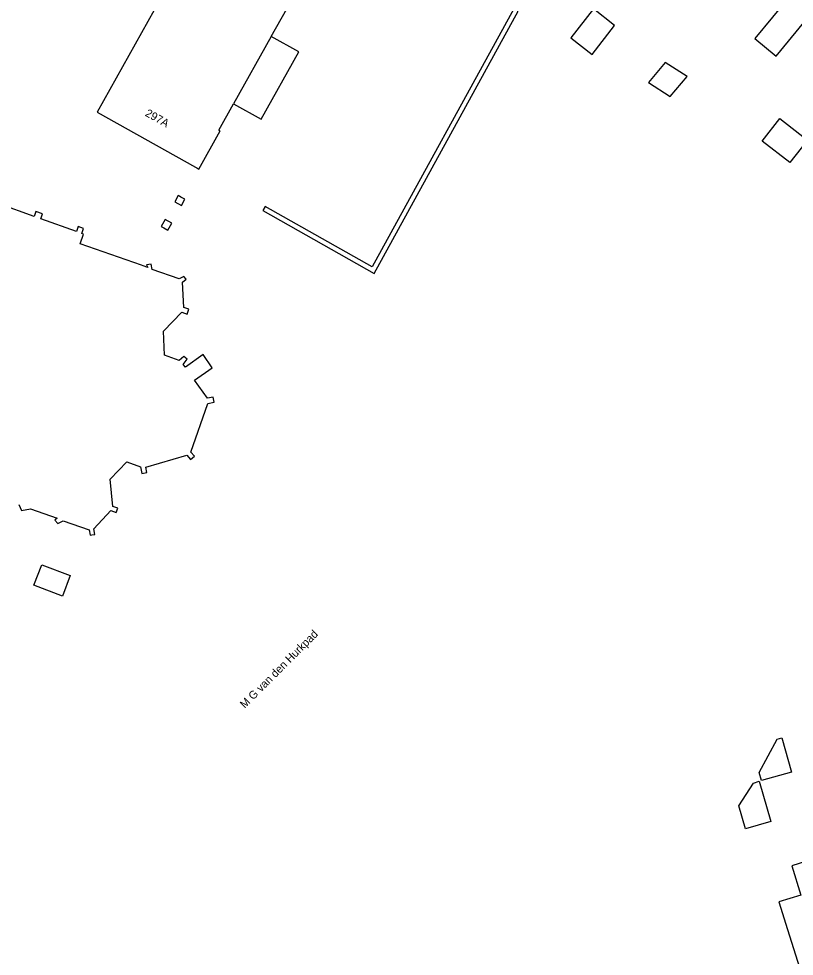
# Model space of a CAD drawing. Extents: x 160158 to 160921, y 381517 to 382041.
# Drawn here: x 160328.3 to 160425.2, y 381721.4 to 381838.6 of the extents above; entities that cross this region are included whole.
import ezdxf

# ---------------------------------------------------------------- set-up
doc = ezdxf.new("R2010")
doc.units = 0
for name, color, linetype in [('IMGEO_Haag', 7, 'Continuous'), ('IMGEO_Openbare_ruimte_label', 7, 'Continuous'), ('IMGEO_Pand', 7, 'Continuous'), ('IMGEO_Pand_nummerreeks', 7, 'Continuous')]:
    doc.layers.add(name, color=color, linetype=linetype)

msp = doc.modelspace()

# ---------------------------------------------------------------- linework, layer by layer
at = {"layer": 'IMGEO_Haag'}
msp.add_lwpolyline([(160390.71, 381839.51), (160390.18, 381839.81), (160372.47, 381807.57), (160359.11, 381815.11), (160358.81, 381814.59), (160372.7, 381806.75), (160390.71, 381839.51)], dxfattribs=at)
at = {"layer": 'IMGEO_Pand'}
for points in [[(160433.66, 381851.69), (160430.49, 381847.83), (160428.34, 381845.23), (160427.99, 381845.47), (160424.71, 381841.48), (160420.28, 381836.11), (160422.95, 381833.91), (160427.38, 381839.29), (160430.67, 381843.29), (160433.12, 381841.26), (160435.29, 381843.87), (160438.47, 381847.73)], [(160359.85, 381836.38), (160363.21, 381842.38), (160362.12, 381842.99), (160362.23, 381843.19), (160350.76, 381849.62), (160348.45, 381845.51), (160346.49, 381846.6), (160344.03, 381842.21), (160346.02, 381841.1), (160338.08, 381826.92), (160350.39, 381820.03), (160350.56, 381819.93), (160350.8, 381819.79), (160353.47, 381824.56), (160353.29, 381824.66), (160355.13, 381827.96)], [(160397.29, 381836.18), (160399.95, 381834.11), (160402.77, 381837.74), (160400.11, 381839.81), (160397.29, 381836.18)], [(160359.85, 381836.38), (160355.13, 381827.96)], [(160355.13, 381827.96), (160358.58, 381826.02), (160363.3, 381834.44), (160359.85, 381836.38)], [(160411.82, 381831.37), (160409.1, 381833.11), (160407, 381830.59), (160409.73, 381828.86), (160411.82, 381831.37)], [(160421.2, 381823.29), (160423.42, 381826.12), (160426.86, 381823.42), (160424.65, 381820.59), (160421.2, 381823.29)], [(160348.22, 381816.48), (160347.79, 381815.69), (160348.62, 381815.23), (160349.05, 381816.02), (160348.56, 381816.29), (160348.38, 381816.39), (160348.22, 381816.48)], [(160328.3, 381777.85), (160328.65, 381777.12), (160329.75, 381777.33), (160333.12, 381776.15), (160332.82, 381775.9), (160333.17, 381775.49), (160333.86, 381775.82), (160337.1, 381774.68), (160337.22, 381774.01), (160337.42, 381774.05), (160337.81, 381774.12), (160337.68, 381774.8), (160339.8, 381777.11), (160340.48, 381776.87), (160340.67, 381777.4), (160340.04, 381777.63), (160339.71, 381781.03), (160341.79, 381783.19), (160343.52, 381782.59), (160343.68, 381781.75), (160344.32, 381781.87), (160344.19, 381782.54), (160349.3, 381784.01), (160349.76, 381783.48), (160350.25, 381783.89), (160349.8, 381784.41), (160351.93, 381790.5), (160352.73, 381790.65), (160352.61, 381791.28), (160351.88, 381791.14), (160350.28, 381793.4), (160352.48, 381794.95), (160351.35, 381796.62), (160349.15, 381795.02), (160348.86, 381795.35), (160349.33, 381796.04), (160348.91, 381796.35), (160348.35, 381795.86), (160346.52, 381796.51), (160346.38, 381799.51), (160348.67, 381801.91), (160349.35, 381801.67), (160349.55, 381802.26), (160348.92, 381802.48), (160348.75, 381805.64), (160349.21, 381806.04), (160348.93, 381806.36), (160348.33, 381806.08), (160344.98, 381807.25), (160344.86, 381807.92), (160344.28, 381807.81), (160344.44, 381807.49), (160343.83, 381807.7), (160343.64, 381807.77), (160335.97, 381810.46), (160336.38, 381811.65), (160336.2, 381811.72), (160336.41, 381812.34), (160335.71, 381812.59), (160335.5, 381811.99), (160331.04, 381813.55), (160331.27, 381814.21), (160330.45, 381814.5), (160330.23, 381813.88), (160325.79, 381815.43)], [(160346.58, 381813.49), (160346.11, 381812.63), (160346.27, 381812.54), (160346.44, 381812.45), (160346.95, 381812.17), (160347.42, 381813.03), (160346.58, 381813.49)], [(160330.18, 381767.76), (160331.18, 381770.31), (160334.73, 381768.97), (160333.77, 381766.39), (160330.18, 381767.76)], [(160423.66, 381748.7), (160424.88, 381744.42), (160421.12, 381743.35), (160420.83, 381744.37), (160423.09, 381748.53), (160423.66, 381748.7)], [(160420.12, 381743.05), (160420.84, 381743.26), (160422.28, 381738.23), (160419.11, 381737.32), (160418.29, 381740.18), (160420.12, 381743.05)], [(160427.91, 381733.64), (160424.9, 381732.68), (160426.05, 381729.05), (160423.3, 381728.18), (160424.38, 381724.75), (160425.89, 381719.98), (160431.07, 381721.62)]]:
    msp.add_lwpolyline(points, dxfattribs=at)

# ---------------------------------------------------------------- texts
at = {"layer": 'IMGEO_Openbare_ruimte_label'}
msp.add_text('M G van den Hurkpad', height=1, rotation=45, dxfattribs=at).set_placement((160356.54, 381752.32))
at = {"layer": 'IMGEO_Pand_nummerreeks'}
msp.add_text('297A', height=1, rotation=330.7505, dxfattribs=at).set_placement((160344.01, 381826.49))

doc.saveas('drawing.dxf')
